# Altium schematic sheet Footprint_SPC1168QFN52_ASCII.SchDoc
size A4; 项目编号: SPSZ2023-052501A; 项目名称: 三相PFC-2.2KW压机+700W风机
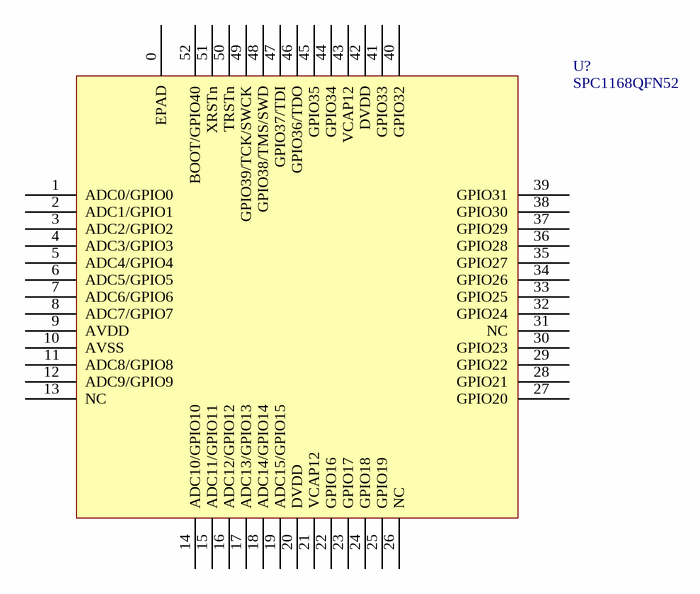
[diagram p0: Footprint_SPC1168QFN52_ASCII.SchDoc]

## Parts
U?  SPC1168QFN52  [QFN-52-0.4]

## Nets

Not connected (* = marked no-connect by the designer): U? 0(EPAD) 1(ADC0/GPIO0) 2(ADC1/GPIO1) 3(ADC2/GPIO2) 4(ADC3/GPIO3) 5(ADC4/GPIO4) 6(ADC5/GPIO5) 7(ADC6/GPIO6) 8(ADC7/GPIO7) 9(AVDD) 10(AVSS) 11(ADC8/GPIO8) 12(ADC9/GPIO9) 13(NC) 14(ADC10/GPIO10) 15(ADC11/GPIO11) 16(ADC12/GPIO12) 17(ADC13/GPIO13) 18(ADC14/GPIO14) 19(ADC15/GPIO15) 20(DVDD) 21(VCAP12) 22(GPIO16) 23(GPIO17) 24(GPIO18) 25(GPIO19) 26(NC) 27(GPIO20) 28(GPIO21) 29(GPIO22) 30(GPIO23) 31(NC) 32(GPIO24) 33(GPIO25) 34(GPIO26) 35(GPIO27) 36(GPIO28) 37(GPIO29) 38(GPIO30) 39(GPIO31) 40(GPIO32) 41(GPIO33) 42(DVDD) 43(VCAP12) 44(GPIO34) 45(GPIO35) 46(GPIO36/TDO) 47(GPIO37/TDI) 48(GPIO38/TMS/SWD) 49(GPIO39/TCK/SWCK) 50(TRSTn) 51(XRSTn) 52(BOOT/GPIO40)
